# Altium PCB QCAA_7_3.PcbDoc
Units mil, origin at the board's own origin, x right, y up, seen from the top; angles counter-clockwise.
Board outline 636.93 x 714.73 mil, 2 copper layers (Top Layer, Bottom Layer); 41 components, 41 nets, 165 pads, 56 vias.
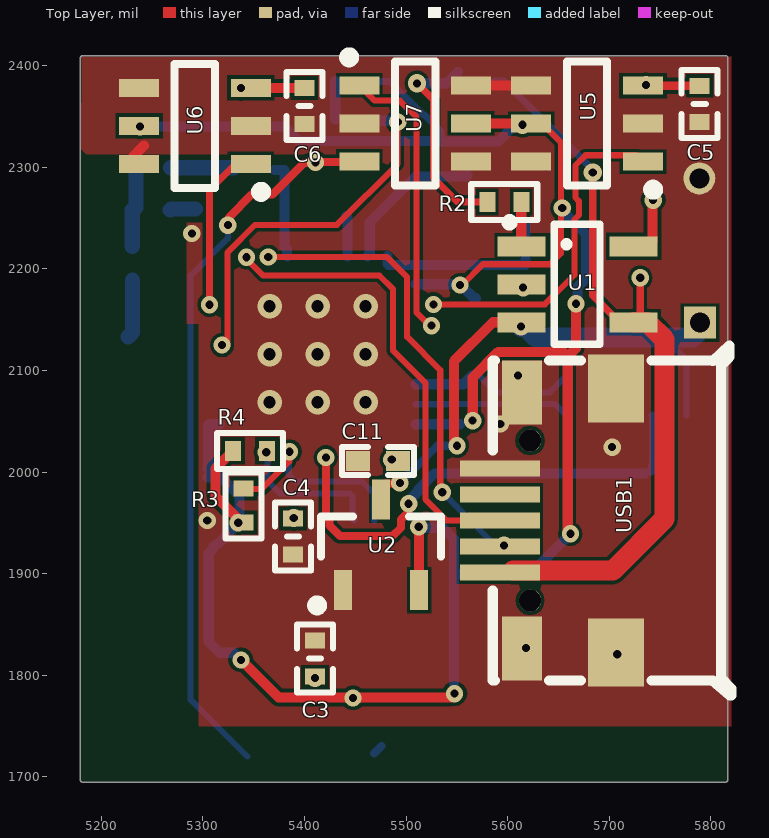
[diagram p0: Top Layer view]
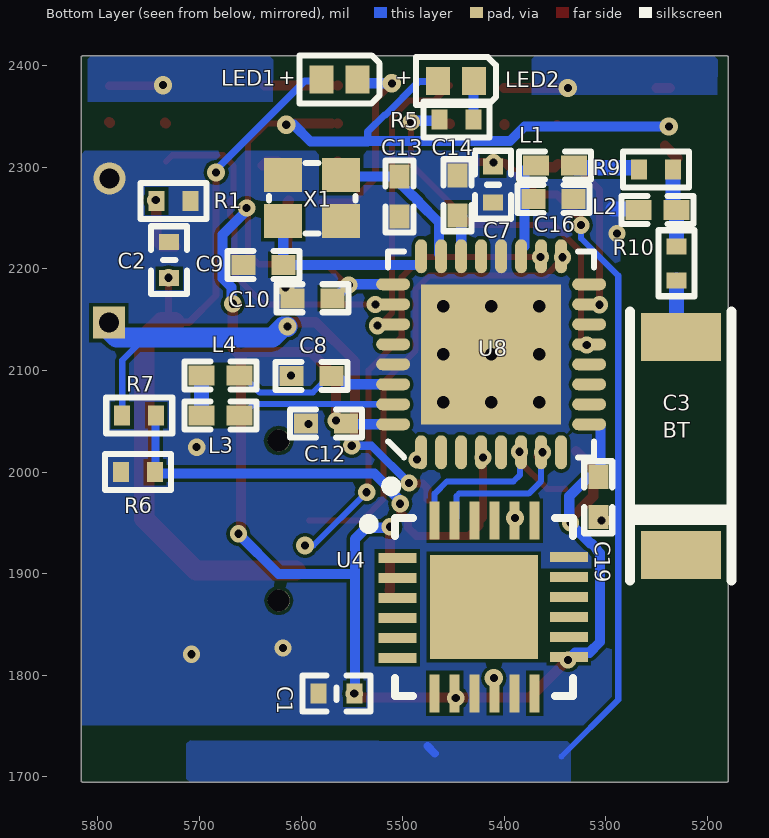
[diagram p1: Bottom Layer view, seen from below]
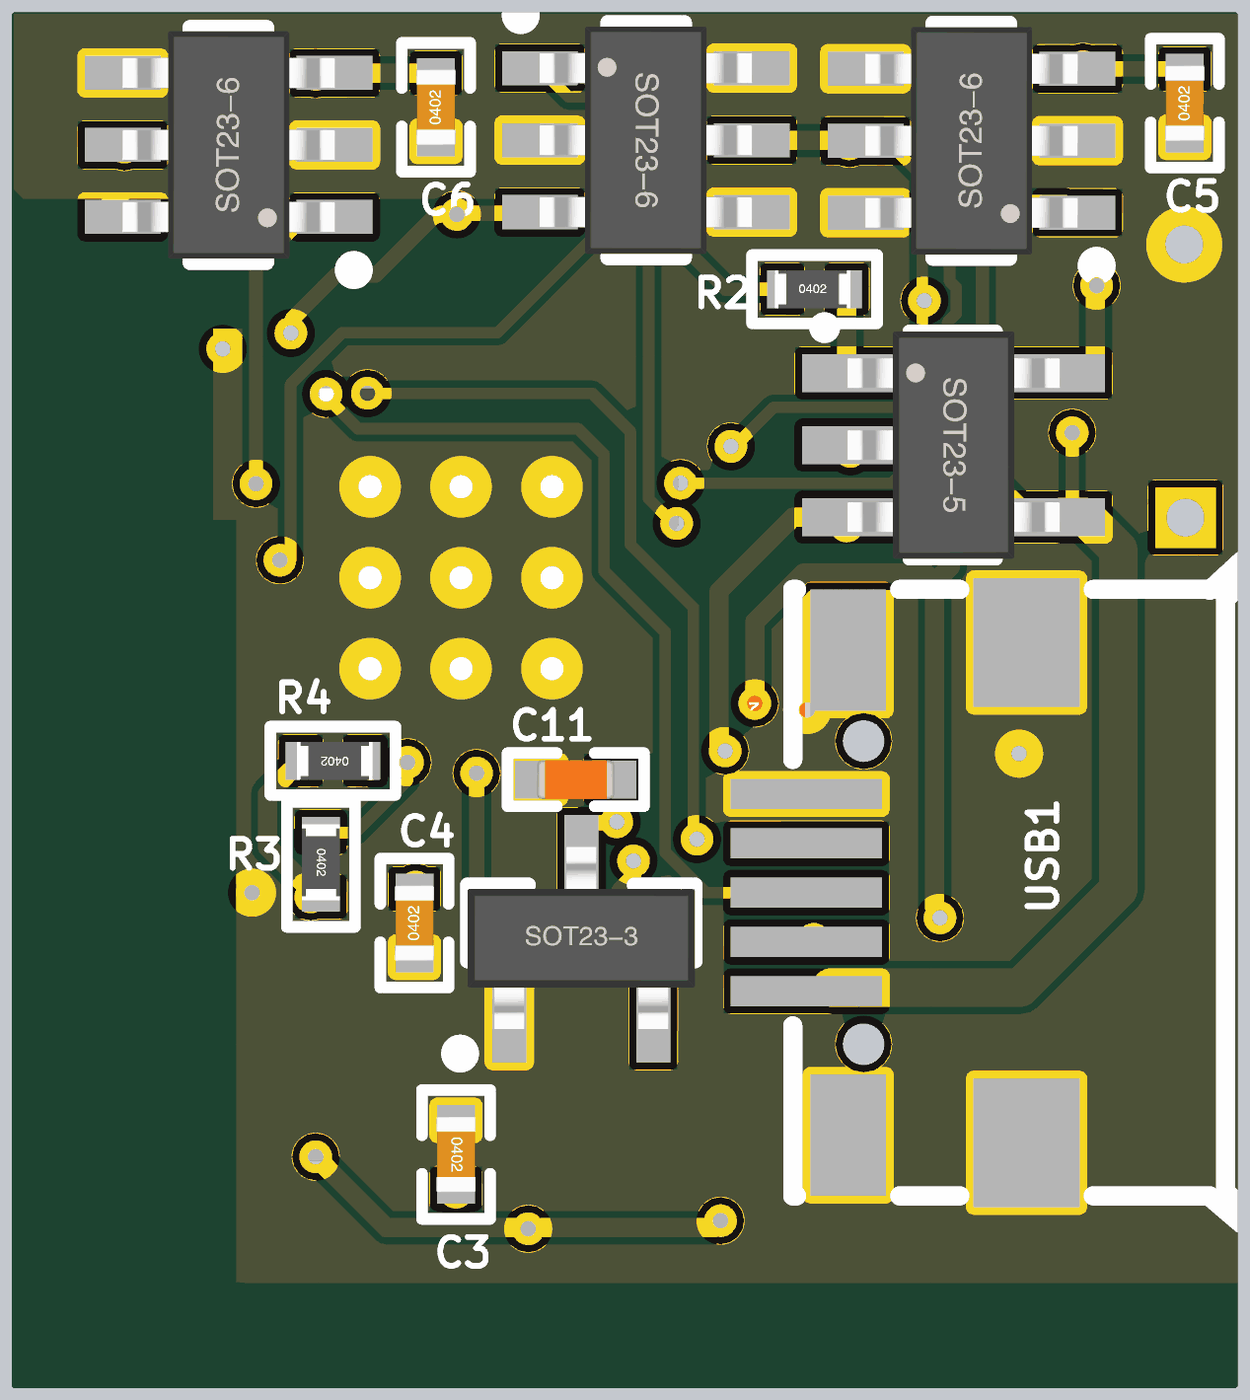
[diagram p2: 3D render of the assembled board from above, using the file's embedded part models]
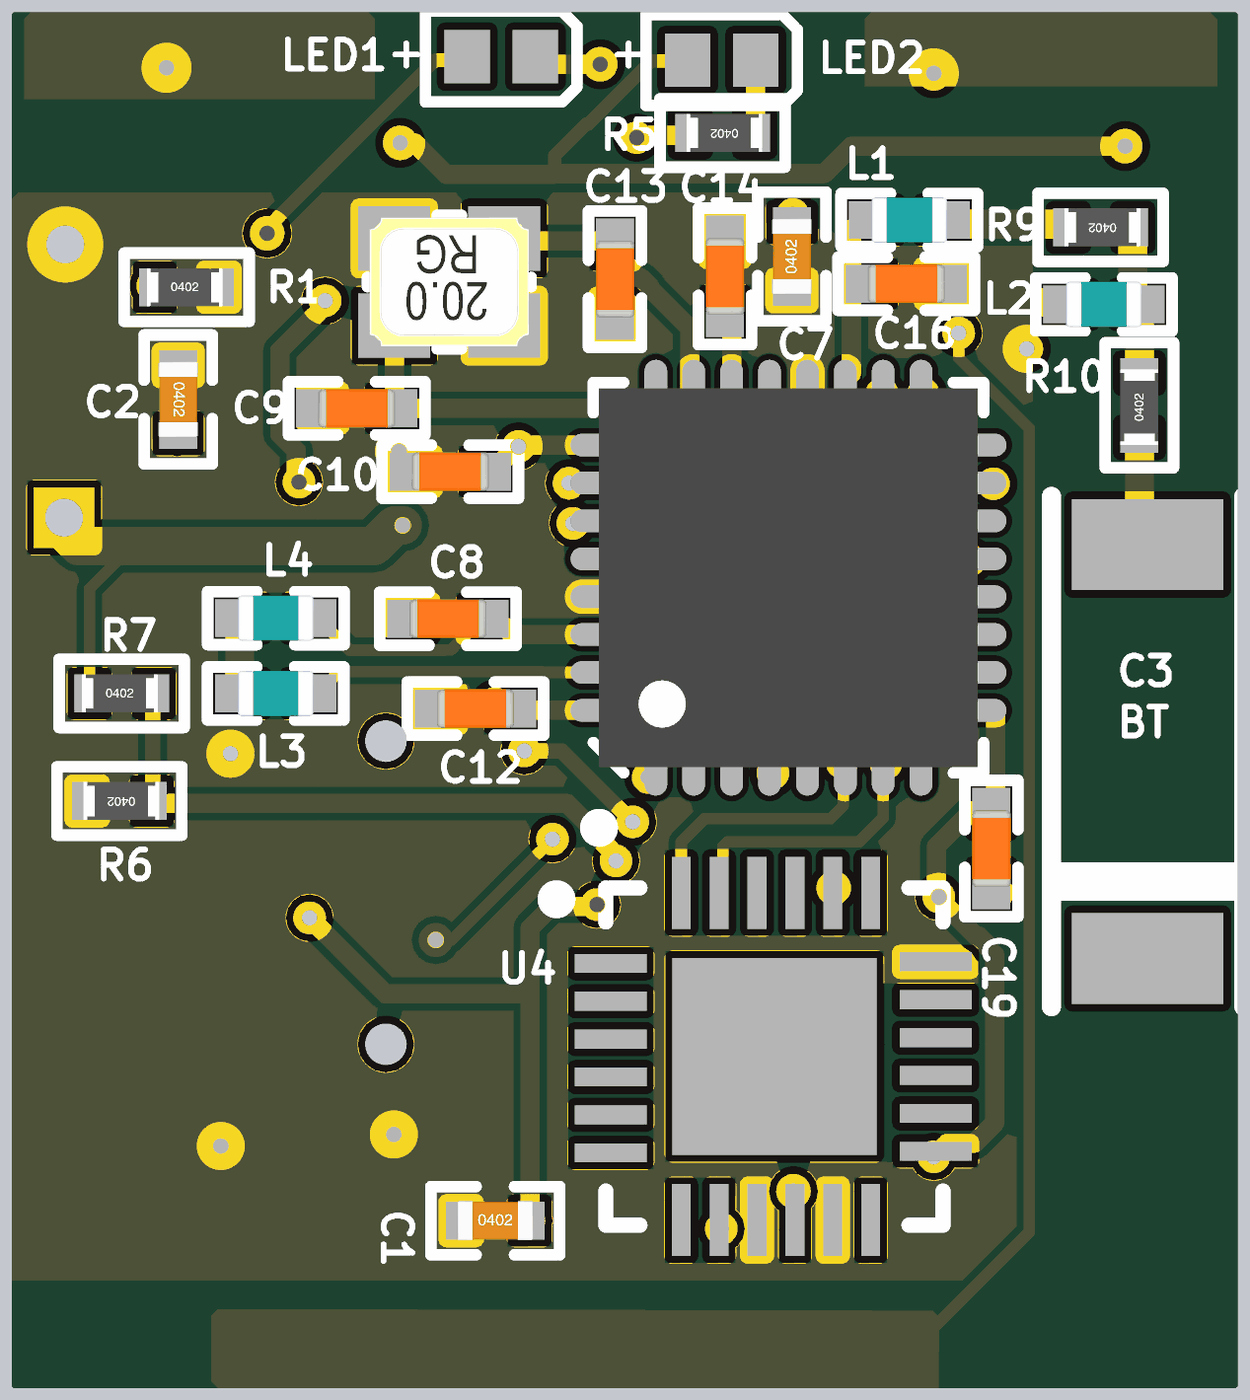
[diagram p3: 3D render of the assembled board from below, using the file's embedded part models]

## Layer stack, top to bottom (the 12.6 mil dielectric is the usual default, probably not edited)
Top Solder: solder mask 0.4, Solder Resist, Dk 3.5
Top Layer: signal copper 1.4
Dielectric 1: dielectric 12.6, FR-4, Dk 4.8
Bottom Layer: signal copper 1.4
Bottom Solder: solder mask 0.4, Solder Resist, Dk 3.5

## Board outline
5179.59,1696.5 5179.59,2408.1 cw(c5181.1,2408.1) 5180.03,2409.17 5180.13,2409.27 cw(c5181.2,2408.2) 5181.2,2409.72 5815,2409.72 cw(c5815,2408.2) 5816.52,2408.2 5816.52,1696.5 cw(c5815,1696.5) 5815,1694.98 5181.1,1694.98 cw(c5181.1,1696.5)

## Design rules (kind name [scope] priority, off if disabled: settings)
Clearance [All] p1: gap=3.5 ignorepadtopadclearanceinfootprint=TRUE except(5: Arc-Via Track-Via)
MinimumSolderMaskSliver [All] p1: minsoldermaskwidth=0
PlaneConnect [All] p1: planeconnectstyle=Direct reliefexpansion=20 reliefentries=4 reliefconductorwidth=10 reliefairgap=10
PolygonConnect [All] p1: connectstyle=Direct reliefconductorwidth=10 reliefentries=4 polygonreliefangle="90 Angle" airgapwidth=10
RoutingVias [All] p1: holewidth=28 width=50 viastyle="Through Hole" minholewidth=3 minwidth=0 maxholewidth=28 maxwidth=50
SilkToSilkClearance [All] p1: silktosilkclearance=0
SilkToSolderMaskClearance [IsPad] p1: minsilkscreentomaskgap=0 clearancetoexposedcopper=TRUE
SolderMaskExpansion [All] p1: expansion=4
Width [All] p1: maxlimit=20 minlimit=6 preferedwidth=10
26 further rules are at their usual default settings.

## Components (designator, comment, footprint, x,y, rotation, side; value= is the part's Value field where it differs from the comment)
BT "ANT1" CA-C03 5296.4,1963.2 r180 bottom (schematic designator Bluetooth1)
C1 "1uF" "C 0402_L" 5565.3,1782 r180 bottom
C2 "1uF" "C 0402_L" 5730,2208.6 r270 bottom
C3 "100nF" "C 0402_L" 5410.4,1816.4 r270 top
C4 "2.2nF" "C 0402_L" 5388.8,1936.6 r90 top
C5 "10uF" "C 0402_L" 5789,2362.5 r90 top
C6 "5uF" "C 0402_L" 5400,2360.4 r90 top
C7 "10uF" "C 0402_L" 5411.2,2282.9 r90 bottom
C8 "1.0µF" CAPC1005X04L 5589.9,2094.7 r180 bottom value=1.0μF
C9 "12pF" CAPC1005X04L 5637.3,2204 r0 bottom
C10 "100nF" CAPC1005X04L 5588.7,2171.1 r0 bottom
C11 "100nF" CAPC1005X04L 5472.6,2011.1 r180 top
C12 "4.7µF" CAPC1005X04L 5575.6,2048 r0 bottom value=4.7μF
C13 "12pF" CAPC1005X04L 5503.1,2271.1 r270 bottom
C14 "100pF" CAPC1005X04L 5446,2272.5 r90 bottom
C16 "0.8pF" CAPC1005X04L 5351.8,2268.7 r0 bottom
C19 "100nF" CAPC1005X04L 5307.6,1975.3 r270 bottom
L1 "3.9nH" INDC1005X04L 5350.2,2301.8 r180 bottom
L2 "3nH" INDC1005X04L 5249.2,2258 r180 bottom value=3.9nH
L3 "10µH" INDC1005X04L 5679.4,2055.9 r180 bottom value=10μH
L4 "15nH" INDC1005X04L 5679.3,2095 r0 bottom
LED1 "红色" LED2-0R6X1R0 5562.2,2386.7 r180 bottom
LED2 "蓝色" LED2-0R6X1R0 5447.7,2384.9 r180 bottom
R1 "2K" "R 0402_L" 5726.6,2266.9 r180 bottom
R2 "3.3K" "R 0402_L" 5595.7,2265.9 r0 top
R3 "4.7K" "R 0402_L" 5340.2,1968.1 r270 top
R4 "4.7K" "R 0402_L" 5347.4,2020.9 r180 top
R5 "3.3K" "R 0402_L" 5446.3,2347 r0 bottom
R6 "1M" "R 0402_L" 5759.6,2000 r0 bottom
R7 "1M" "R 0402_L" 5760.4,2055.9 r180 bottom
R9 "Res2" "R 0402_L" 5249.9,2298 r0 bottom value=0
R10 "Res2" "R 0402_L" 5230.7,2204.6 r90 bottom value=0
U1 "HX4054A" SOT23-5N 5668.9,2184.9 r270 top
U2 "XC6206P332MR" SOT23-3L 5475.5,1928.8 r0 top
U4 "MPU6050" MPU6050 5420.3,1867.27 r180 bottom
U5 "TTP223" SOT23-6L 5678.2,2343 r90 top
U6 "TTP223" SOT23-6L 5292.3,2340.8 r90 top
U7 "TTP223" SOT23-6L 5509,2343.3 r270 top
U8 "nRF52810-QCAA" Nordic_QFN50P500X500X90-33N 5413,2116 r90 bottom
USB1 "USB-5P" MICRO-USB-SMD_MICROQTJ 5649.6,1952.4 r90 top
X1 "32MHz" BT-XTAL_2016 5589.2,2269.6 r0 bottom

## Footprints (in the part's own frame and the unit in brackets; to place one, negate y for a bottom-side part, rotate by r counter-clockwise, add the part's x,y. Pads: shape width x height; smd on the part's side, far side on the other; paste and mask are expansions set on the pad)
BT-XTAL_2016 [mm]
  rect 0.95x0.85 smd: 1(-0.725,-0.575) 2(0.725,-0.575) 3(0.725,0.575) 4(-0.725,0.575)
  silkscreen extent -1.08,-0.88 1.08,0.88, body extent -1.05,-0.85 1.05,0.85, height 0.56
"C 0402_L" [mm] "无极性贴片电容"
  rect 0.4x0.5 smd: 1(-0.45,0) 2(0.45,0)
  silkscreen extent -0.85,-0.45 0.85,0.45, body extent -0.5,-0.26 0.5,0.26, height 0.53
CA-C03 [mil] "CA-C03  2.4G SMD antenna"
  rect 78.74x47.24 smd: 1(70,-45) 2(70,170)
  silkscreen extent 20,-70 120,195
CAPC1005X04L [mm]
  rect 0.6x0.5 smd: 1(-0.5,0) 2(0.5,0)
  silkscreen extent -0.9,-0.35 0.9,0.35, body extent -0.51,-0.25 0.51,0.25, height 0.5
INDC1005X04L [mm]
  rect 0.65x0.5 smd: 1(-0.475,0) 2(0.475,0)
  silkscreen extent -0.9,-0.35 0.9,0.35, body extent -0.5,-0.3 0.5,0.3, height 0.5
LED2-0R6X1R0 [mm]
  rect 0.6x0.7 smd: 1(-0.45,0) 2(0.45,0)
  silkscreen extent -1,-0.6 1,0.6
MICRO-USB-SMD_MICROQTJ [mm]
  rect 0.4x2 smd: 1(-1.3,1.452) 2(-0.65,1.452) 3(0,1.452) 4(0.65,1.452) 5(1.3,1.452)
  rect 1.7x1.4 smd: 5(-3.3,-1.452) 5(3.3,-1.452)
  rect 1.6x1 smd: 5(-3.2,0.902) 5(3.2,0.902)
  round 0.55 hole 0.55 unplated: ""(-2,0.698) ""(2,0.698)
  silkscreen extent -4.37,-4.34 4.38,1.63
MPU6050 [mm] "QFN, 24-Leads, Body 4.00x4.00mm, Pitch 0.50mm, Thermal Pad 2.70x2.60mm, IPC Medium Density"
  rect 0.95x0.25 smd: 1(-2.159,1.23) 2(-2.159,0.73) 3(-2.159,0.23) 4(-2.159,-0.27) 5(-2.159,-0.77) 6(-2.159,-1.27) 13(2.127,-1.25) 14(2.127,-0.75) 15(2.127,-0.25) 16(2.127,0.25) 17(2.127,0.75) 18(2.127,1.25)
  rect 0.25x0.95 smd: 7(-1.23,-2.159) 8(-0.73,-2.159) 9(-0.23,-2.159) 10(0.27,-2.159) 11(0.77,-2.159) 12(1.27,-2.159) 19(1.27,2.159) 20(0.77,2.159) 21(0.27,2.159) 22(-0.23,2.159) 23(-0.73,2.159) 24(-1.23,2.159)
  rect 2.7x2.6 smd: 25(0,0)
  silkscreen extent -3,-2.22 2.22,2.23, body extent -2.08,-2.07 2.07,2.08, height 0.9
Nordic_QFN50P500X500X90-33N [mm]
  oval 0.85x0.3 smd mask+0.076: 1(-2.45,1.75) 2(-2.45,1.25) 3(-2.45,0.75) 4(-2.45,0.25) 5(-2.45,-0.25) 6(-2.45,-0.75) 7(-2.45,-1.25) 8(-2.45,-1.75) 17(2.45,-1.75) 18(2.45,-1.25) 19(2.45,-0.75) 20(2.45,-0.25) 21(2.45,0.25) 22(2.45,0.75) 23(2.45,1.25) 24(2.45,1.75)
  oval 0.3x0.85 smd mask+0.076: 9(-1.75,-2.45) 10(-1.25,-2.45) 11(-0.75,-2.45) 12(-0.25,-2.45) 13(0.25,-2.45) 14(0.75,-2.45) 15(1.25,-2.45) 16(1.75,-2.45) 25(1.75,2.45) 26(1.25,2.45) 27(0.75,2.45) 28(0.25,2.45) 29(-0.25,2.45) 30(-0.75,2.45) 31(-1.25,2.45) 32(-1.75,2.45)
  rect 3.5x3.5 smd: 33(0,0)
  silkscreen extent -3.42,-2.57 2.57,2.63, body extent -2.5,-2.5 2.5,2.5, height 0.9
"R 0402_L" [mm] "1/16W贴片电阻"
  rect 0.4x0.5 smd: 1(-0.4,0) 2(0.45,0)
  silkscreen extent -0.8,-0.45 0.85,0.45, body extent -0.5,-0.25 0.5,0.25, height 0.3
SOT23-3L [mm] "3x1.3x1mm(长宽高)"
  rect 0.45x1 smd: 1(-0.95,-1.143) 2(0.95,-1.143) 3(0,1.125)
  silkscreen extent -1.72,-1.65 1.5,0.7, body extent -1.5,-1.2 1.5,1.2, height 1.05
SOT23-5N [mm] "3x1.6x1.1mm(长宽高)"
  rect 0.5x1.2 smd: 1(-0.95,-1.4) 2(0,-1.4) 3(0.95,-1.4) 4(0.95,1.4) 5(-0.95,1.4)
  silkscreen extent -1.63,-1.78 1.5,0.56, body extent -1.5,-1.4 1.5,1.4, height 1.15
SOT23-6L [mm] "3x1.6x1.1mm(长宽高)"
  rect 0.45x1 smd: 1(-0.95,-1.397) 2(0,-1.397) 3(0.95,-1.397) 4(0.95,1.397) 5(0,1.397) 6(-0.95,1.397)
  silkscreen extent -1.77,-1.78 1.55,0.51, body extent -1.5,-1.4 1.5,1.4, height 1.15

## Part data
BT: library part BLUETOOTH_ANT, "PCB板载天线"
C1 C2 C3 C4 C5 C6 C7: library part C, "无极性贴片电容"
C8: library part C0603-1μ0, "Capacitor, X7R, ±10%"
C9 C13: library part C0402-12p, "Capacitor, NP0, ±2%"
C10 C11 C19: library part C0402-100n, "Capacitor, X7R, ±10%"
C12: library part C0603-4μ7, "Capacitor, X5R, ±10%"
C14: library part C0402-100p, "Capacitor, NP0, ±5%"
C16: library part C0402-0.8p, "Capacitor, NP0, ±5%"
L1 L2: library part L0402-3n9, "High frequency chip inductor ±5%"
L3: library part L0603-10μ, "Chip inductor, IDC,min = 50 mA, ±20%"
L4: library part L0402-15n, "High frequency chip inductor ±10%"
LED1 LED2: library part LED-SMD, "贴片LED"
R1 R2 R3 R4 R5 R6 R7: library part R, "贴片电阻"
R9 R10: "Resistor"
U1: library part MCP73831/2, "Li-on Charging IC"
U2: "DC-DC Linear IC / Cheap"
U4: "Three-axis MEMS IC"
U5 U6 U7: library part TTP223E-BA6, "Touching switch IC"
U8: "Multi-protocol Bluetooth Low Energy, ANT and 2.4GHz proprietary system-on-chip", Manufacturer="Nordic Semiconductor"
USB1: "微型USB母座"
X1: library part XTAL_SMD2016_32MHz_8pF_General, "XTAL SMD 2016, 32MHz, Cl=8pF, Total Tol: ±40ppm"

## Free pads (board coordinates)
  rect 31.5x31.5 hole 19.68: 14(5789.3,2147.2)
  round 31.5 hole 19.68: 15(5788.7,2289.1)

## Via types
v1: diameter 17, hole 8, Top Layer to Bottom Layer, 37 vias
v2: diameter 24, hole 12, Top Layer to Bottom Layer, 9 vias
v3: diameter 18, hole 8, Top Layer to Bottom Layer, 8 vias
v4: diameter 17.72, hole 7.87, Top Layer to Bottom Layer, tented both sides, 2 vias

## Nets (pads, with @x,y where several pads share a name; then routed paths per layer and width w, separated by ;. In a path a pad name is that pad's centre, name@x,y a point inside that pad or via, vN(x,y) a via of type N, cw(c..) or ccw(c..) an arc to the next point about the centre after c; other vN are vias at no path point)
+3.3V: C1.2 C10.1 C12.1 C19.1 LED2.1 R3.2 R4.2 U2.2 U4.8 U4.13 U5.5 U6.5 U7.5 U8.9 U8.25 U8.32 | length 2352.3
  Top Layer w6: v1(5553.2,2184.2) 5555.2,2184.2 5575.6,2204.6 5641.7,2204.6 5652.5,2215.4 5652.5,2324.53 5634.03,2343 U5.5
  Top Layer w10: R4.2 5312.5,2003.72 5312.5,1976.12 R3.2@5338.23,1950.39 ; v1(5337.5,1815.2) 5374.4,1778.3 v1@5544.3,1778.3 ; v1(5512.5,1946.2) 5512.75,1945.95 U2.2@5512.75,1886.8 ; U2.2@5512.75,1883.65 U2.2 ; U7.5 U7.5@5564.15,2343.15 ; v1(5565.6,2050.7) 5565.6,2093.08 5590.9,2118.38 5654.42,2118.38 5659.1,2113.7 ; U7.5@5570.45,2343.15 U5.5@5614.7,2343.15 ; v1@5659.1,1944.1 5659.1,2113.7 ; v1(5667.3,2165.7) 5667.3,2121.9 5659.1,2113.7
  Bottom Layer w7: LED2.1@5466.32,2384.43 5484.32,2384.43 5517.11,2351.64 5518.06,2351.64 5534.5,2335.2 5534.5,2325.9 5534.9,2325.5
  Bottom Layer w10: v3(5238.1,2340.2) 5380.23,2340.2 5394.53,2325.9 5534.5,2325.9 ; C19.1@5304.8,1994.88 5317.61,1994.88 5336.1,1976.4 5336.1,1950.44 5315.57,1929.91 5314.34,1929.91 5309.36,1924.93 5309.36,1923.7 5305.9,1920.24 5305.9,1832.76 5316.41,1822.25 5330.45,1822.25 v1(5337.5,1815.2) ; C19.1@5304.9,2003.29 5305.37,2003.75 5305.37,2046.27 5306.21,2047.1 U8.9 ; U8.32 C12.1@5553.25,2047.1 ; U8.25 v1@5553.2,2184.9 ; v1(5512.5,1946.2) 5513.4,1945.3 5536,1945.3 5547.2,1934.1 5547.2,1899.8 ; 5534.9,2325.5 5590.8,2325.5 5607.2,2341.9 v3(5614.7,2341.9) ; 5547.2,1792.3 5547.2,1899.8 ; v1(5553.2,2184.2) 5553.95,2184.2 5567.05,2171.1 C10.1 ; v1(5653.7,2259.9) 5653.7,2257.5 5677.3,2233.9 5677.3,2190.64 5668.64,2181.98 5668.64,2167.04 v1(5667.3,2165.7) ; v1(5661.8,1939.3) 5622.3,1899.8 5547.2,1899.8
  other v1: 5447.9,1777.8 5547.8,1782 5334.9,1950.2
blue: R5.2 U8.13 | length 362.7
  Top Layer w6: v1@5324.4,2124.9 5324.4,2216.33 5351.37,2243.3 5431.97,2243.3 5491.8,2303.13 v1(5491.8,2344.6)
  Bottom Layer w10: R5.2 5465.21,2345.8 5488.57,2345.8 v1@5489.55,2346.78
  other v1: 5318.9,2125.1
DEC1: C11.1 U8.1
  other v1: 5485.9,2012.3
DEC2: U8.21
DEC3: C14.1 U8.22 | length 40.2
  Bottom Layer w10: C14.1@5441.1,2252.11 5442.53,2250.69 U8.22
DEC4: C8.2 L4.1 U8.30 | length 163.3
  Bottom Layer w6: C8.2 5572.18,2094.7 5588.38,2078.5 5591.6,2078.5 5591.74,2078.36 5641,2078.36 5657.65,2095 L4.1 L4.1@5660.3,2094.7
  Bottom Layer w10: U8.30 5556.47,2086.47 C8.2@5564.8,2094.8
Detection: R6.1 R7.2 U8.4 | length 478.2
  Top Layer w8: v1(5421.1,2014.5) 5421.1,1955.45 5424.62,1951.93 5424.62,1947.38 5435,1937 5486.7,1937 5495,1945.3 5495,1953.45 5502.6,1961.05 v1(5502.6,1968.9)
  Bottom Layer w8: R7.2 5743.31,2055.27 R6.1@5743.31,2007.02
  Bottom Layer w10: v1@5499.6,1968.3 5499.6,1968.74 5512.4,1981.54 5512.4,1983.16 5527.94,1998.7 5734.99,1998.7 ; R6.1@5741.06,2001.56 5743.31,2003.81 R6.1@5743.31,2007.02
GND: C1.1 C2.1 C3.1 C4.1 C5.1 C6.1 C7.1 C8.1 C9.2 C10.2 C11.2 C12.2 C13.2 C14.2 C16.1 C19.2 L2.1 pad.15 R1.2 R6.2 U1.2 U2.1 U4.9 U4.11 U4.18 U5.2 U5.4 U5.6 U6.2 U6.4 U6.6 U7.2 U7.4 U7.6 U8.20 U8.29 U8.33 USB1.5 X1.2 X1.4 | length 145.3
  Top Layer w10: U6.6@5229.75,2308.95 5242,2321.2 ; U6.4 U6.4@5250.1,2378.2 ; U6.2 U6.2@5348.24,2341.74 ; C6.1@5400,2341.74 C6.1 ; U7.2@5453.38,2342.68 U7.2 ; U7.4 U7.4@5564.15,2305.75 ; U7.6 U7.6@5564.15,2380.55 ; U7.6@5570.45,2380.55 5623.05,2380.55 U5.4 U5.4@5635.8,2380.4 ; U5.6@5623.05,2305.75 U5.6 ; U5.6@5624.5,2304.3 U5.6 ; U5.6@5637.89,2301.74 5634.03,2305.6 U5.6 ; U5.2 U5.2@5734.09,2343.89 ; C5.1@5788.11,2343.89 C5.1
  Bottom Layer w15: L2.1 5268.9,2259 5292.8,2259
  other v1: 5707.9,1820.8 5618,1826.8 5304.4,1952.4 5702.9,2024.6 5592.8,2047.3 5610.2,2095 5615.3,2181.6 5289.2,2234.9
  other v2: 5365.76,2068.76 5413,2068.76 5460.24,2068.76 5365.76,2116 5413,2116 5460.24,2116 5365.76,2163.24 5413,2163.24 5460.24,2163.24
NetBluetooth1_2: BT.2 R10.1 | length 57.4
  Bottom Layer w15: BT.2 5230.7,2137.5 R10.1
NetC3_2: C3.2 U4.10
  other v3: 5410.4,1797.3
NetC4_2: C4.2 U4.20
  other v3: 5389.5,1954.8
NetC5_2: C5.2 U5.3 | length 55.9
  Top Layer w8: U5.3 5733.29,2380.31 5788.91,2380.31 C5.2
  other v3: 5736.1,2380.9
NetC6_2: C6.2 U6.3 | length 53
  Top Layer w10: U6.3 U6.3 5400.26,2378.16 C6.2@5400.3,2378.11
  other v3: 5337.5,2378
NetC7_2: C7.2 U7.3 | length 729.8
  Top Layer w8: v1@5325.6,2243 5325.6,2250.7 5348.07,2273.17 5368.49,2273.17 5399.43,2304.11 5401.4,2304.11 ; 5402,2304.71 5402.6,2305.31 5453.41,2305.31 U7.3
  Bottom Layer w6: v1(5324.6,2243.1) 5324.6,2230.2 5287.9,2193.5 5287.9,1776 5343.8,1720.1
  Bottom Layer w8: 5468.5,1723.2 5475.8,1730.5
  other v1: 5410.8,2304.7
NetC16_2: C16.2 L1.1 U8.19 | length 96
  Bottom Layer w10: L1.1@5370.4,2297.4 5380,2297.4 5380.3,2297.1 5380.3,2222.06 5382.9,2219.46 5382.9,2213.03 U8.19
NetL1_2: L1.2 R9.2 | length 61.9
  Bottom Layer w15: R9.2@5268.32,2299.7 L1.2@5330.2,2299.7
NetL2_2: L2.2 R9.1 R10.2 | length 76
  Bottom Layer w15: R10.2 5230.6,2222.41 5230.6,2257.9 L2.2 5231.81,2258 5234.15,2260.34 R9.1@5234.15,2296
NetL3_1: L3.1 L4.2 | length 39.1
  Bottom Layer w10: L4.2 L4.2@5698.05,2094.95 ; L3.1@5698.05,2055.95 L3.1
  Bottom Layer w15: L3.1@5698.05,2055.95 L4.2@5698.05,2094.95
NetL3_2: L3.2 U8.31 | length 156.1
  Bottom Layer w6: U8.31 5540.74,2066.79 5541.15,2067.2 5646.45,2067.2 5657.75,2055.9 L3.2
NetLED1_2: LED1.2 R2.1 | length 207.5
  Top Layer w7: v3(5510.8,2382.7) 5527,2366.5 5527,2289.4 5550.5,2265.9 R2.1
  Bottom Layer w10: v3(5510.8,2382.7) 5539.9,2382.7 LED1.2@5550.97,2393.77
NetLED2_2: LED2.2 R5.1 | length 38.1
  Bottom Layer w10: LED2.2 5430.27,2384.62 5430.27,2347.29 R5.1
NetR1_1: R1.1 U1.5 | length 61.4
  Top Layer w10: U1.5 5737.8,2222.3 5742.64,2227.14 5742.64,2267.14 v1(5743.2,2267.7)
NetR2_2: R2.2 U1.1 | length 45.5
  Top Layer w10: R2.2@5612.2,2267.11 R2.2 5613.41,2222.67 U1.1
P0.05/AIN3: U8.5
P0.10: U8.8
P0.12: U8.10
P0.14: U8.11
P0.15: U8.12
P0.18: U8.14
P0.30/AIN6: U8.28
Q1: U6.1 U8.15 | length 178.9
  Top Layer w7: v1(5306.5,2164.8) 5306.5,2277.9 5332,2303.4 U6.1
  Top Layer w10: U6.1 5350.6,2300.1 U6.1@5360.4,2300.1
Q2: U5.1 U8.26 | length 334.9
  Top Layer w6: v1(5527,2165.1) 5636.64,2165.1 5665.8,2194.26 5665.8,2248.67 5670.2,2253.07 5670.2,2266.73 5666.8,2270.13 5666.8,2301.94 5676.76,2311.9 5726.9,2311.9 U5.1
Q3: U7.1 U8.27 | length 292.4
  Top Layer w6: U7.1 5469,2365.7 5494.03,2365.7 5510.5,2349.23 5510.5,2156.97 5523.27,2144.2 v1(5525,2144.2)
  Top Layer w7: U7.1 U7.1@5464.83,2380.7
SCL: R4.1 U4.23 U8.7 | length 153
  Top Layer w10: R4.1@5363.25,2018.5 R4.1@5366.13,2015.63
  Bottom Layer w6: U8.7 5363.79,1991.21 5376.2,1978.8 5444.69,1978.8 5447.12,1976.37 5447.12,1954.2 U4.23 U4.23@5449.04,1958.52
  other v1: 5362.4,2019.6
SDA: R3.1 U4.24 U8.6 | length 206.7
  Top Layer w6: R3.1 5340.55,1983.5 5358,1983.5 5385.2,2010.7 v1(5385.2,2020.1)
  Bottom Layer w6: U8.6 5384.58,2018.43 5384.58,1997.42 5391.2,1990.8 5456.65,1990.8 5468.73,1978.73 U4.24
SWDCLK: U8.17 USB1.3 | length 460.2
  Top Layer w6: v1(5342.9,2211.5) 5342.9,2209.97 5359.47,2193.4 5473.9,2193.4 5487.3,2180 5487.3,2119.6 5519.1,2087.8 5519.1,1973.37 5540.07,1952.4 USB1.3
SWDIO: U8.18 USB1.2 | length 452.1
  Top Layer w6: v1(5364.4,2211.8) 5481.1,2211.8 5501,2191.9 5501,2133.2 5533.7,2100.5 5533.7,1983.73 v1@5535.83,1981.6
  Bottom Layer w6: v1(5535.6,1980.2) 5588,1927.8 v4(5596.2,1927.8)
  Bottom Layer w10: v4(5596.2,1927.8) v4@5596.36,1927.96
USB_Power: C2.2 LED1.1 U1.4 USB1.1 | length 738.7
  Top Layer w7: v3(5683.8,2294.9) 5683.8,2173.94 5710.24,2147.5 U1.4 5724.16,2147.5 5730.5,2153.84 v1(5730.5,2191.3)
  Top Layer w20: USB1.1@5605.35,1903.12 5703.48,1903.12 5754.4,1954.03 5754.4,2130.58 5737.48,2147.5 U1.4@5724.16,2147.5
  Bottom Layer w7: LED1.1@5586.57,2384.87 5596.47,2384.87 5683.8,2297.55 v3(5683.8,2294.9)
VBAT: pad.14 R7.1 U1.3 U2.3 | length 542.7
  Top Layer w8: U2.3 5475.5,1983.92 5480.36,1988.78 5493.48,1988.78 v1(5493.9,1989.2)
  Top Layer w10: v1@5547.1,2027.8 5547.1,2109 5585.6,2147.5 U1.3
  Bottom Layer w6: 5753.8,2132.47 5776.15,2110.11 R7.1
  Bottom Layer w8: v1(5493.9,1989.2) 5530.7,2026 v1(5550.2,2026)
  Bottom Layer w20: v4(5613.4,2143.2) 5617.6,2143.2 5628.33,2132.47 5753.8,2132.47 5781.77,2132.47 pad.14@5794,2144.7
XC1: C13.1 U8.23 X1.1 | length 150.1
  Bottom Layer w10: U8.23 5464.34,2214.59 5464.34,2245.73 5484.76,2266.14 5484.76,2266.75 5489.74,2271.73 5490.34,2271.73 5509.5,2290.89 5559.3,2290.89 X1.1
XC2: C9.1 U8.24 X1.3 | length 186.7
  Bottom Layer w10: U8.24 5481.9,2204.84 5482.73,2204 C9.1 5617.61,2246.83 X1.3
pads on no net: BT.1 U4.1 U4.2 U4.3 U4.4 U4.5 U4.6 U4.7 U4.12 U4.14 U4.15 U4.16 U4.17 U4.19 U4.21 U4.22 U4.25 U8.2 U8.3 U8.16 USB1. USB1.4

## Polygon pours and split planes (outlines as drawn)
GND on Bottom Layer "Bottom Layer-GND" (solid, pour order 68): 5180.2,2316.2 5818.7,2316.2 5819.5,2315.4 5816.6,2312.5 5816.6,1750.9 5183,1750.9 5180.9,1753
NetC5_2 on Bottom Layer "Bottom Layer-NetC5_2" (solid, pour order 60): 5627.73,2409.59 5809.96,2409.99 5809.96,2364.5 5627.89,2364.5
NetC6_2 on Bottom Layer "Bottom Layer-NetC5_2" (solid, pour order 56): 5190.13,2409.57 5373.3,2409.97 5373.3,2364.5 5190.28,2364.5
NetC7_2 on Bottom Layer "Bottom Layer-NetC5_2" (solid, pour order 52): 5334.74,1735.29 5712.9,1736.11 5712.9,1694.81 5334.88,1694.81
no net on Bottom Layer "Bottom Layer-No Net 1" (solid, pour order 30): 5474.76,2574.93
no net on Bottom Layer "Bottom Layer-No Net 1" (solid, pour order 28): 5475.16,2546.43
no net on Bottom Layer "Bottom Layer-No Net 2" (solid, pour order 26): 5557.19,2426.67
GND on Top Layer "Top Layer-GND" (solid, pour order 64): 5180.7,2409 5819.9,2409 5819.9,1749.7 5183.2,1749.7 5179.8,1753.1
no net on Top Layer "Top Layer-No Net" (solid, pour order 42): 5639.4,2417.4

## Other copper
Top Layer:
  pour cut-out: 5283.09,2145.9 5296.2,2145.9 5296.2,1750.11 5283.09,1750.11
  pour cut-out: 5180,2313.8 5180.9,2312.9 5399.3,2312.9 5399.3,2245.4 5284.1,2245.4 5284.1,1693.1 5282.4,1694.8 5179.5,1694.8 5179.5,2311.6 5180,2312.1
Bottom Layer:
  pour cut-out: 5179,2372.25 5179.9,2371.35 5398.3,2371.35 5398.3,2303.85 5389.7,2295.25 5286.1,2295.25 5286.1,1754.55 5283.1,1751.55 5281.4,1753.25 5178.5,1753.25 5178.5,2370.05 5179,2370.55

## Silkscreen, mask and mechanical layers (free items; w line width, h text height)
Mechanical 1:
  lines w3: 5815,1935.2 5815,2408.2 5181.2,2408.2 5181.1,2408.1 5181.1,1696.5 5815,1696.5 5815,1937.21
